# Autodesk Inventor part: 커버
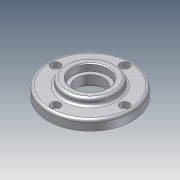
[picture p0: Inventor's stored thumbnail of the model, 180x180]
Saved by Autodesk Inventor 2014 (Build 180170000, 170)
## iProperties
Company: 한국ATC센터
Created: 2013-01
Part Number: 커버
Document SubType Name: Modeling
Designer: KYOUNG IL JANG
Density: 1 g/cm^3
Material: 일반
Appearance: 기본값
Author: KYOUNG IL JANG
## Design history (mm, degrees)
sketch "스케치1"
  geometry: C1 r 31 at (0, 0) reference; C2 r 50 at (0, 0); 1 further point
  constraints: 1 centre point, 1 coincident
  dimensions: "d41" = 100 diameter of C2
extrude "돌출1" new body sketch "스케치1" distance "d0" = 12; taper "d1" = 0 deg
sketch "스케치2"
  geometry: C1 r 30 at (0, 0); 1 further point
  constraints: 1 centre point, 1 coincident
  dimensions: "d2" = 60 diameter of C1
extrude "돌출2" join sketch "스케치2" distance "d3" = 8; taper "d4" = 0 deg
fillet "모깎기1" dims "d5" = 3
sketch "스케치3" dims "d42" = 82
  geometry: 3 further points
  constraints: 2 vertical alignment, 1 coincident, 2 other
hole "구멍1" sketch "스케치3" at (0, 41) diameter "d6" = 6.6; stored, may be unused: countersink angle "d10" = 90 deg, drill point angle "d12" = 118 deg; dims "d7" = 6, "d8" = 11, "d9" = 6.5, "d11" = 8
hole "구멍2" diameter "d18" = 33; stored, may be unused: countersink angle "d22" = 90 deg, drill point angle "d24" = 118 deg; dims "d16" = 10, "d17" = 10, "d19" = 6, "d20" = 42, "d21" = 8.5, "d23" = 8
sketch "스케치4"
  geometry: C1 r 31 at (0, 0) reference; C2 r 22.5 at (0, 0); 1 further point
  constraints: 1 centre point, 1 coincident
  dimensions: "d43" = 45 diameter of C2
extrude "돌출3" join sketch "스케치4" distance "d25" = 6; taper "d26" = 0 deg
hole "구멍3" diameter "d29" = 50; stored, may be unused: countersink angle "d33" = 90 deg, drill point angle "d35" = 0 deg; dims "d27" = 10, "d28" = 10, "d30" = 6, "d31" = 42, "d32" = 8.5, "d34" = 7
fillet "모깎기2" dims "d36" = 3, "d37" = 0.3
chamfer "모따기1" distance "d38" = 1; stored, may be unused: second distance "d39" = 2, angle "d40" = 45 deg
node "솔리드1"
pattern_circular "원형 패턴1" dims angle "d14" = 360 deg
node "참조9"
node "참조11"
